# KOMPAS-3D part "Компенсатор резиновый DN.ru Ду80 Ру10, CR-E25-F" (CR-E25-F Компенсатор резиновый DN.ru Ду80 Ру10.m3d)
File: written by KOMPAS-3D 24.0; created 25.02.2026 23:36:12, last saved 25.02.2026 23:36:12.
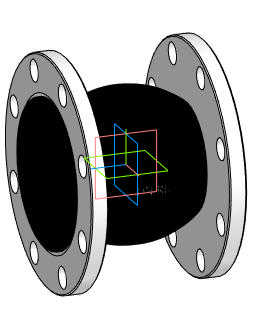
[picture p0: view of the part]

Document properties: Автор: DN.RU; Полное имя файла: D:\PROJECT CAD\DN.RU\...178(4)(ACTUALE). CR-E25-F Компенсатор резиновый DN.ru Ру10-16\DN80_PN10\CR-E25-F Компенсатор резиновый DN.ru Ду80 Ру10.m3d

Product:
- Body: Твердое тело2  | qty 1
    Масса: 8.814168
- Part/product: Компенсатор резиновый DN.ru Ду80 Ру10  | designation CR-E25-F
    Масса: 7.04
    Раздел спецификации: Прочие изделия
    Комментарий: D140-02164
    Примечание: D140-02164
    additional columns: Типовые

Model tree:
1. Твердое тело2  (labels: Твердое тело2)

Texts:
  CR-E25-F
